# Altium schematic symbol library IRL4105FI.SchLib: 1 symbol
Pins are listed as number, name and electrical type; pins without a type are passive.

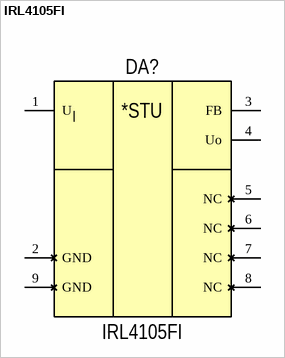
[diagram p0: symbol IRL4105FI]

## IRL4105FI
designator DA?
Микросхема линейного регулятора напряжения; TemperatureOperating: - 40°C to + 85°C
pins: 1 U, 2 GND, 3 FB, 4 Uo, 5 NC, 6 NC, 7 NC, 8 NC, 9 GND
